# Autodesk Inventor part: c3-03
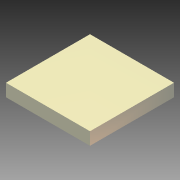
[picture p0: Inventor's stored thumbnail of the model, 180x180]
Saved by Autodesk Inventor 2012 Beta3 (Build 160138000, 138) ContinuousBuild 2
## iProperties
Created: 2010-11
Part Number: c3-03
Material: Cast Iron
Document SubType Name: Modeling
Designer: Beta-8540w
Density: 7.25 g/cm^3
Mass: 1087.5 g
Surface Area: 260 cm^2
Volume: 150 cm^3
Author: Beta-8540w
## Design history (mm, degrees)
sketch "Sketch1"
  geometry: L1 (-50, -50)-(50, -50); L2 (50, -50)-(50, 50); L3 (50, 50)-(-50, 50); L4 (-50, 50)-(-50, -50); 3 further points
  constraints: 8 end point, 3 perpendicular, 2 midpoint, 1 horizontal, 1 horizontal alignment, 1 parallel, 1 vertical alignment
  dimensions: "Width" = 100 distance of L1.start L1.end
extrude "Extrusion1" new body sketch "Sketch1" distance "d3" = 15; taper "d4" = 0 deg
body "Solid1"
